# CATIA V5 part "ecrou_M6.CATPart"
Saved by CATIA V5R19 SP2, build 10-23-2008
Part number: FR_10015 (M6 nut)
Publications: "FaceRondelle", "AxeVis"
Bounding box of the stored display mesh (mm): x -5 to 5, y -5.774 to 5.774, z 0 to 5.2
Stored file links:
  C:\DATA\ecole\ECL\EPSA\Git\ELIZ-2021\Insertion_visserie\visserie\MacroInsertion\catalogue_visserie_outils\Ecrou\Standard\ecrou_M6.CATPart
  C:\Users\Brice\Documents\cours_centrale\S8\maquette numérique\Vis parametrique\parametreEcrou.xlsx
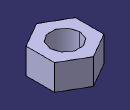
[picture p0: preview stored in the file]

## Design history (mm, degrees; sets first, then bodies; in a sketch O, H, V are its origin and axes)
Parameters
  largeur = 10 mm
  hauteur = 5.2 mm
  diametreInterieur = 6 mm
Body1 (main body)
  Sketch1 on xy-plane, origin (0, 0, 0), H (1, 0, 0), V (0, 1, 0)
    point P1 (5, -2.8868)
    point P2 (5, 2.8868)
    point P3 (0, 5.7735)
    point P4 (-5, 2.8868)
    point P5 (-5, -2.8868)
    point P6 (0, -5.7735)
    point P7 (5, 0)
    line L1 (5, -2.8868) -> (5, 2.8868)
    line L2 (5, 2.8868) -> (0, 5.7735)
    line L3 (0, 5.7735) -> (-5, 2.8868)
    line L4 (-5, 2.8868) -> (-5, -2.8868)
    line L5 (-5, -2.8868) -> (0, -5.7735)
    line L6 (0, -5.7735) -> (5, -2.8868)
    construction line L7 (0, 0) -> (5, 0)
    construction circle A1 centre (0, 0) radius 5.7735
    construction arc A2 centre (-5, -2.8868) radius 5.7735 from (-5, 2.8868) to (0, -5.7735) cw
    construction arc A3 centre (5, 2.8868) radius 5.7735 from (0, 5.7735) to (5, -2.8868) ccw
    circle A4 centre (0, 0) radius 3
    radius A4 = 3 {= diametreInterieur /2}
    distance L2 L5 = 10 {= largeur}
    horizontal: L7 H
    coincidence: A1 P1, A1 P2, A1 P3, A1 P4, A1 P5, A1 P6, A2 O, A3 O
    midpoint: P7 L1
    parallelism: L1 L4
  Pad1: profile Sketch1, direction (0, 0, 1), length 5.2 {= hauteur}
